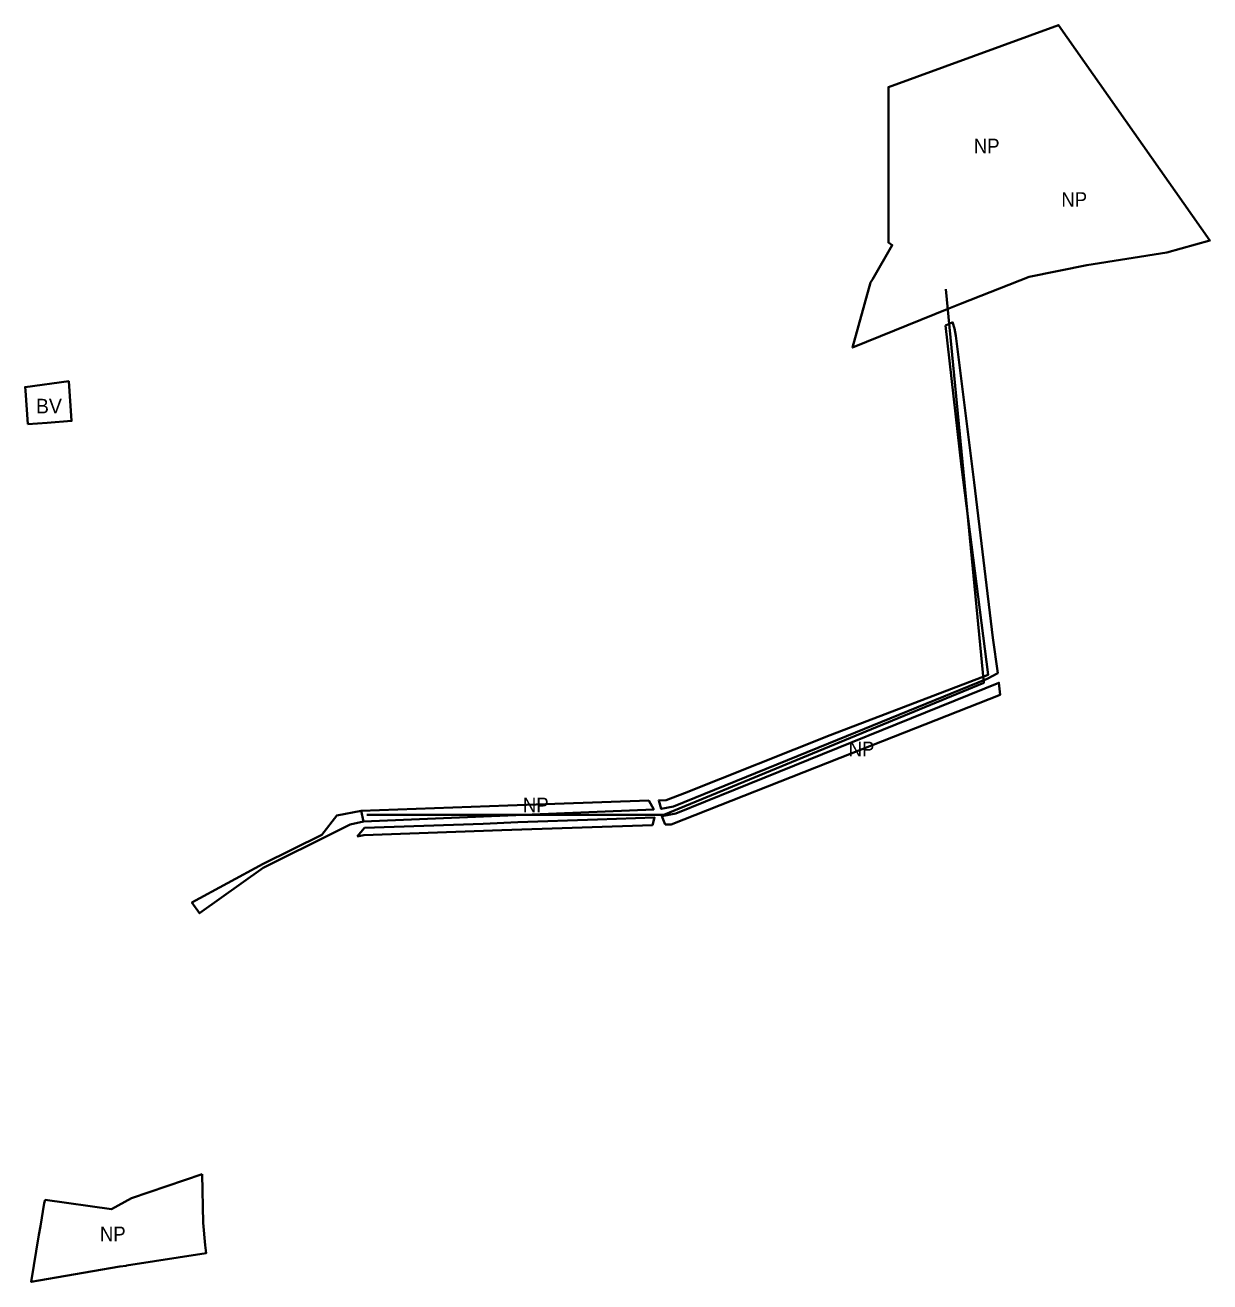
# Model space of a CAD drawing. Extents: x -650276 to -642489, y -1074311 to -1066658.
# Drawn here: x -643464 to -642489, y -1070593 to -1069560 of the extents above; entities that cross this region are included whole.
import ezdxf

# ---------------------------------------------------------------- set-up
doc = ezdxf.new("R2010")
doc.units = 0
doc.header["$LTSCALE"] = 4.8
for name, color, linetype, lineweight in [('15', 7, 'Continuous', 35), ('3', 7, 'Continuous', 35), ('48', 7, 'Continuous', 35), ('54', 7, 'Continuous', 35)]:
    doc.layers.add(name, color=color, linetype=linetype, lineweight=lineweight)
doc.layers.add('62', color=7, linetype='Continuous')

msp = doc.modelspace()

# ---------------------------------------------------------------- linework, layer by layer
at = {"layer": '15', "lineweight": 13}
for points in [[(-643461.327, -1069887.84), (-643445.37, -1069886.7), (-643425.253, -1069885.25), (-643427.6, -1069852.59), (-643463.51, -1069857.44)], [(-643463.51, -1069857.44), (-643463.31, -1069860.18), (-643461.327, -1069887.84)]]:
    msp.add_lwpolyline(points, dxfattribs=at)
at = {"layer": '3'}
msp.add_lwpolyline([(-643461.327, -1069887.84), (-643445.37, -1069886.7), (-643425.253, -1069885.25), (-643427.6, -1069852.59), (-643463.51, -1069857.44), (-643463.31, -1069860.18)], close=True, dxfattribs=at)
at = {"layer": '48'}
for points in [[(-642589.86, -1069757.1), (-642524.14, -1069746.8), (-642488.71, -1069736.85), (-642613.34, -1069559.68), (-642753.18, -1069610.65), (-642753.25, -1069738.59), (-642750.08, -1069740.57), (-642766.27, -1069769), (-642767.89, -1069771.42), (-642782.69, -1069824.93), (-642703.57, -1069792.88), (-642693.99, -1069788.85), (-642637.44, -1069766.81)], [(-642706.3, -1069806.69), (-642693.2, -1069922.89), (-642671.23, -1070094.16), (-642801.19, -1070143.75), (-642921.03, -1070191.32), (-642936.02, -1070197.23), (-642942.12, -1070197.4), (-642940.12, -1070204.42), (-642930.02, -1070202.54), (-642802.38, -1070150.51), (-642671.9, -1070097.32), (-642663.28, -1070092.67), (-642667.19, -1070063.71), (-642682.78, -1069935.98), (-642697.64, -1069815.14), (-642698.77, -1069809.17), (-642700.34, -1069804.12), (-642701.17, -1069804.49)], [(-642936.88, -1070217.27), (-642931.88, -1070217.1), (-642792.87, -1070162.36), (-642661.13, -1070110.48), (-642662.32, -1070100.64), (-642879.2, -1070188.43), (-642928.07, -1070208.21), (-642939.51, -1070210.35)], [(-643066.26, -1070201.69), (-643187.06, -1070205.98), (-643185.16, -1070214.62), (-643086.36, -1070210.57), (-642946.24, -1070204.83), (-642950.42, -1070197.58)], [(-643185.16, -1070214.62), (-643187.06, -1070205.98), (-643207.1, -1070209.72), (-643219.4, -1070225.8), (-643267.55, -1070249.49), (-643326.26, -1070281.43), (-643320, -1070290.2), (-643267.75, -1070252.77), (-643208.09, -1070223.14), (-643196.16, -1070217.22)], [(-643190.42, -1070226.99), (-643184.86, -1070225.91), (-643071.16, -1070221.95), (-642947.42, -1070217.64), (-642945.59, -1070211.49), (-642992.64, -1070213.18), (-643058.07, -1070215.38), (-643086.58, -1070216.57), (-643184.22, -1070220.08)]]:
    msp.add_lwpolyline(points, close=True, dxfattribs=at)
for points in [[(-643452.22, -1070592.35), (-643385.72, -1070580.86), (-643380.35, -1070580.14), (-643380.08, -1070580.09), (-643314.51, -1070569.69), (-643315.27, -1070563.2), (-643317.08, -1070544.75), (-643317.9, -1070504.73)], [(-643317.9, -1070504.73), (-643376.07, -1070524.59), (-643392.41, -1070533.68), (-643446.89, -1070526.01)], [(-643446.89, -1070526.01), (-643447.79, -1070528.63), (-643450.98, -1070547.74), (-643452.14, -1070554.77)], [(-643452.14, -1070554.77), (-643458.42, -1070593.43), (-643452.22, -1070592.35)]]:
    msp.add_lwpolyline(points, dxfattribs=at)
at = {"layer": '54'}
msp.add_lwpolyline([(-643182.326, -1070209.281), (-642937.896, -1070209.281), (-642674.665, -1070100.645), (-642706.002, -1069776.828)], dxfattribs=at)

# ---------------------------------------------------------------- texts
at = {"layer": '62', "width": 0.95}
for p in [(-642682.928, -1069665.096), (-642610.928, -1069709.096), (-642785.928, -1070161.096), (-643053.928, -1070207.096), (-643401.985, -1070559.967)]:
    msp.add_text('NP', height=12, dxfattribs=at).set_placement(p)
at = {"layer": '62'}
msp.add_text('BV', height=12, dxfattribs=at).set_placement((-643454.639, -1069879.037))

doc.saveas('drawing.dxf')
